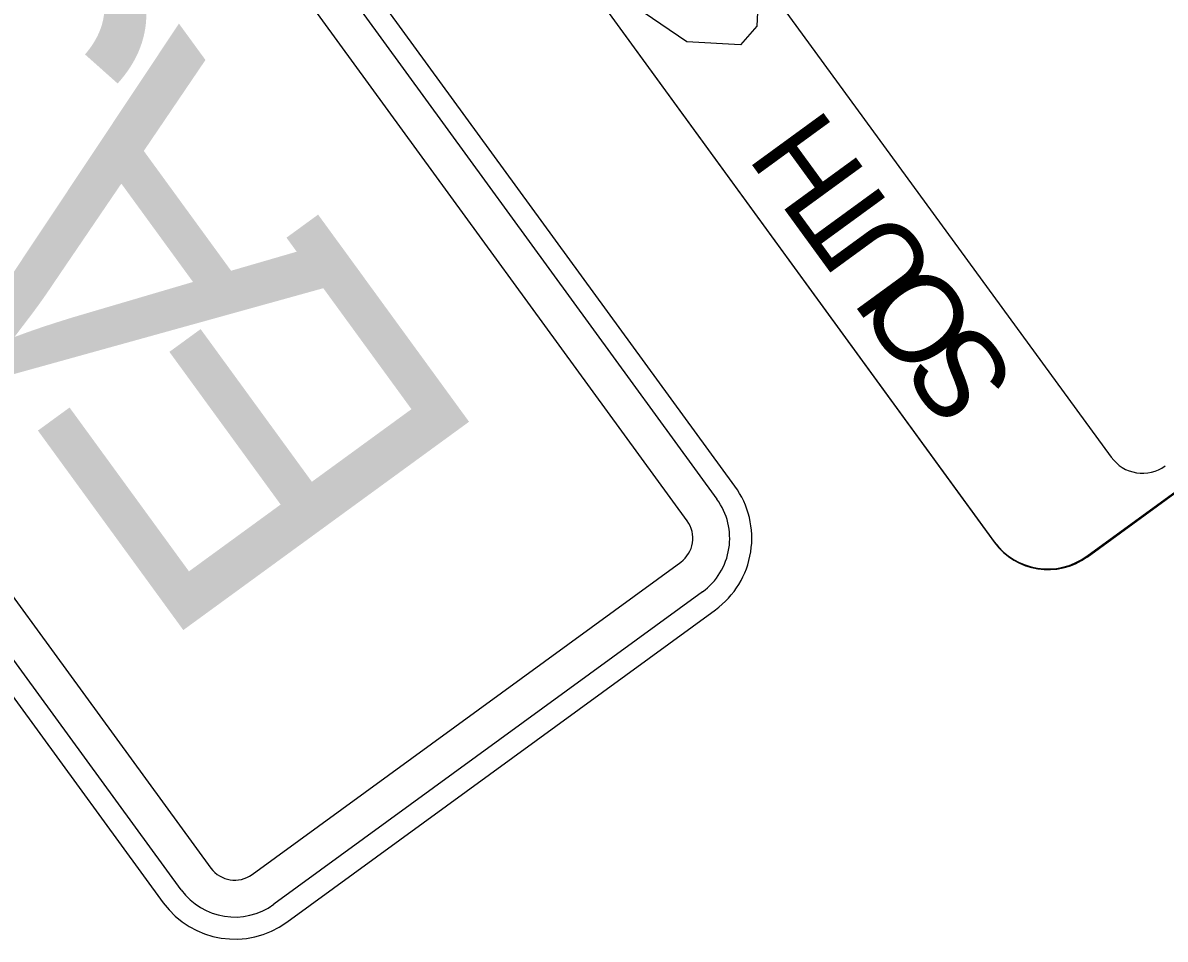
# Model space of a CAD drawing. Extents: x 1581789 to 1622364, y 1043167 to 1103486.
# Drawn here: x 1608827.07 to 1608839.99, y 1092744.25 to 1092754.61 of the extents above; entities that cross this region are included whole.
import ezdxf

# ---------------------------------------------------------------- set-up
doc = ezdxf.new("R2010")
doc.units = 0
doc.layers.add('RD_PD_ALT1_TX', color=7, linetype='Continuous')

msp = doc.modelspace()

# ---------------------------------------------------------------- linework, layer by layer
at = {"layer": 'RD_PD_ALT1_TX'}
for p, q in [((1608827.166, 1092763.684), (1608838.056, 1092748.742)), ((1608827.172, 1092763.676), (1608838.062, 1092748.734)), ((1608839.104, 1092748.577), (1608847.589, 1092754.762)), ((1608839.11, 1092748.569), (1608847.595, 1092754.754))]:
    msp.add_line(p, q, dxfattribs=at)
for points in [[(1608839.383, 1092749.697), (1608835.359, 1092755.212), (1608835.33, 1092755.173), (1608835.423, 1092754.954), (1608835.356, 1092754.836), (1608835.382, 1092754.731), (1608835.372, 1092754.574), (1608835.188, 1092754.362), (1608834.582, 1092754.394), (1608833.994, 1092754.794), (1608833.886, 1092754.8), (1608832.956, 1092756.18), (1608833.109, 1092756.71), (1608832.527, 1092757.538), (1608832.605, 1092757.965), (1608832.742, 1092758.803), (1608828.49, 1092764.637)], [(1608835.124, 1092749.37), (1608826.878, 1092760.684)], [(1608826.676, 1092760.537), (1608834.922, 1092749.223)], [(1608834.585, 1092748.977), (1608826.339, 1092760.291)], [(1608820.951, 1092756.364), (1608829.197, 1092745.051)], [(1608828.861, 1092744.805), (1608820.615, 1092756.119)], [(1608820.413, 1092755.972), (1608828.659, 1092744.658)], [(1608829.663, 1092744.978), (1608834.512, 1092748.512)], [(1608834.757, 1092748.175), (1608829.909, 1092744.641)], [(1608830.056, 1092744.439), (1608834.905, 1092747.973)]]:
    msp.add_lwpolyline(points, dxfattribs=at)
for centre, radius, start, end in [((1608839.736, 1092749.952), 0.436, 215.8565, 305.8567), ((1608834.316, 1092748.781), 1, 306.0865, 36.0867), ((1608834.316, 1092748.781), 0.75, 306.0865, 36.0867), ((1608834.316, 1092748.781), 0.333, 306.0865, 36.0867), ((1608838.663, 1092749.184), 0.75, 216.0868, 306.0865), ((1608838.668, 1092749.176), 0.75, 216.0868, 306.0865), ((1608829.467, 1092745.247), 0.333, 216.0868, 306.0865), ((1608829.467, 1092745.247), 0.75, 216.0868, 306.0865), ((1608829.467, 1092745.247), 1, 216.0868, 306.0865)]:
    msp.add_arc(centre, radius, start, end, dxfattribs=at)

# ---------------------------------------------------------------- texts
for s, height, p in [('S', 4, (1608829.061, 1092754.293)), ('A', 4, (1608830.931, 1092751.727)), ('H', 1, (1608836.632, 1092752.898)), ('T', 1, (1608837.026, 1092752.357)), ('E', 4, (1608832.376, 1092749.744)), ('U', 1, (1608837.448, 1092751.779)), ('O', 1, (1608837.913, 1092751.142)), ('S', 1, (1608838.334, 1092750.563))]:
    msp.add_text(s, height=height, rotation=126.0866, dxfattribs=at).set_placement(p)

doc.saveas('drawing.dxf')
